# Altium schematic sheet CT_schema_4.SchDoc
size 522 x 390 mm
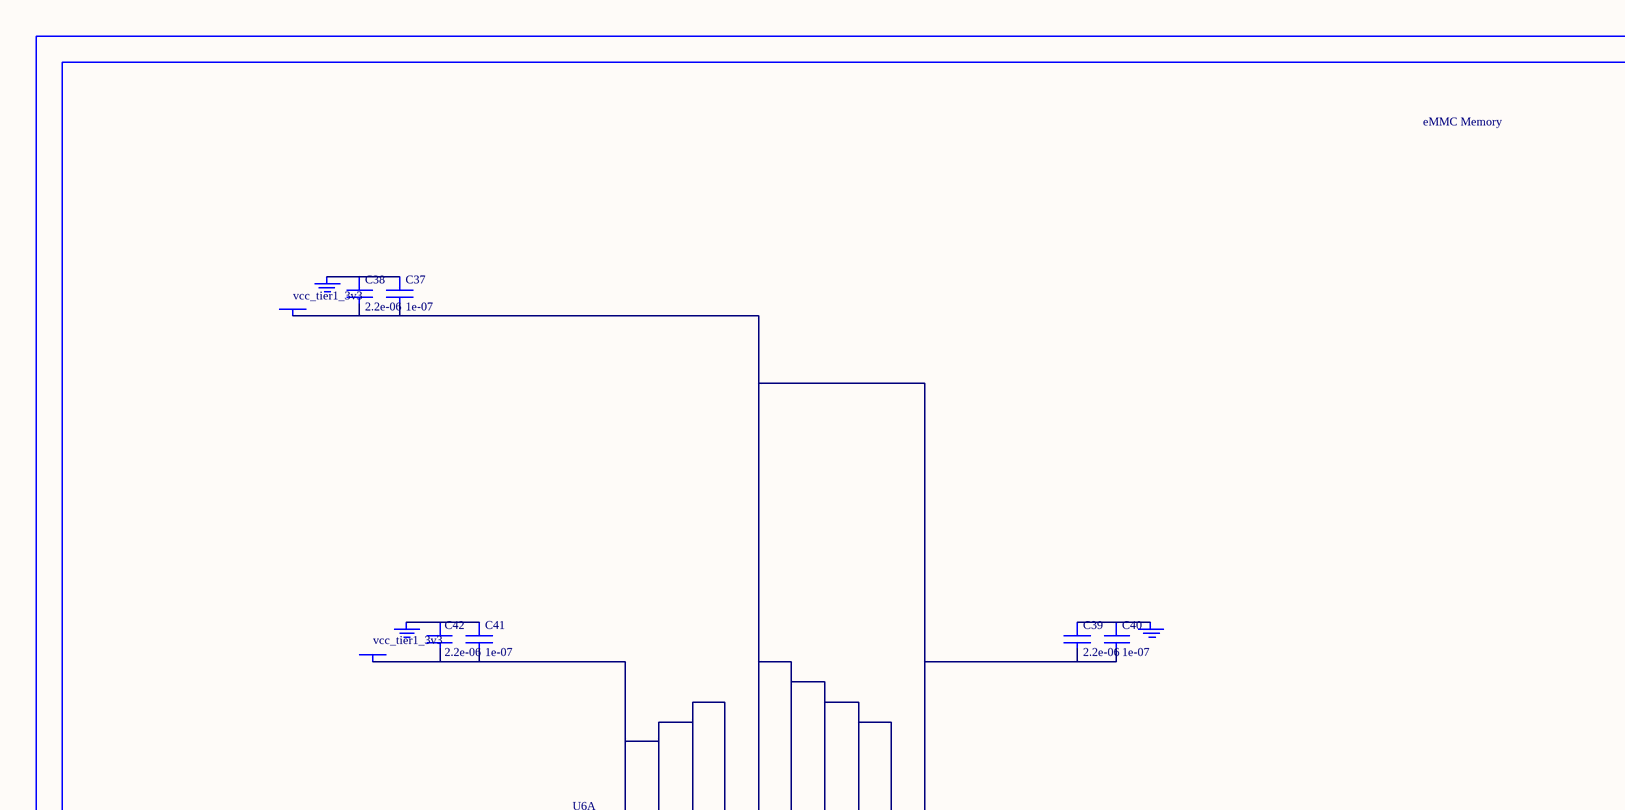
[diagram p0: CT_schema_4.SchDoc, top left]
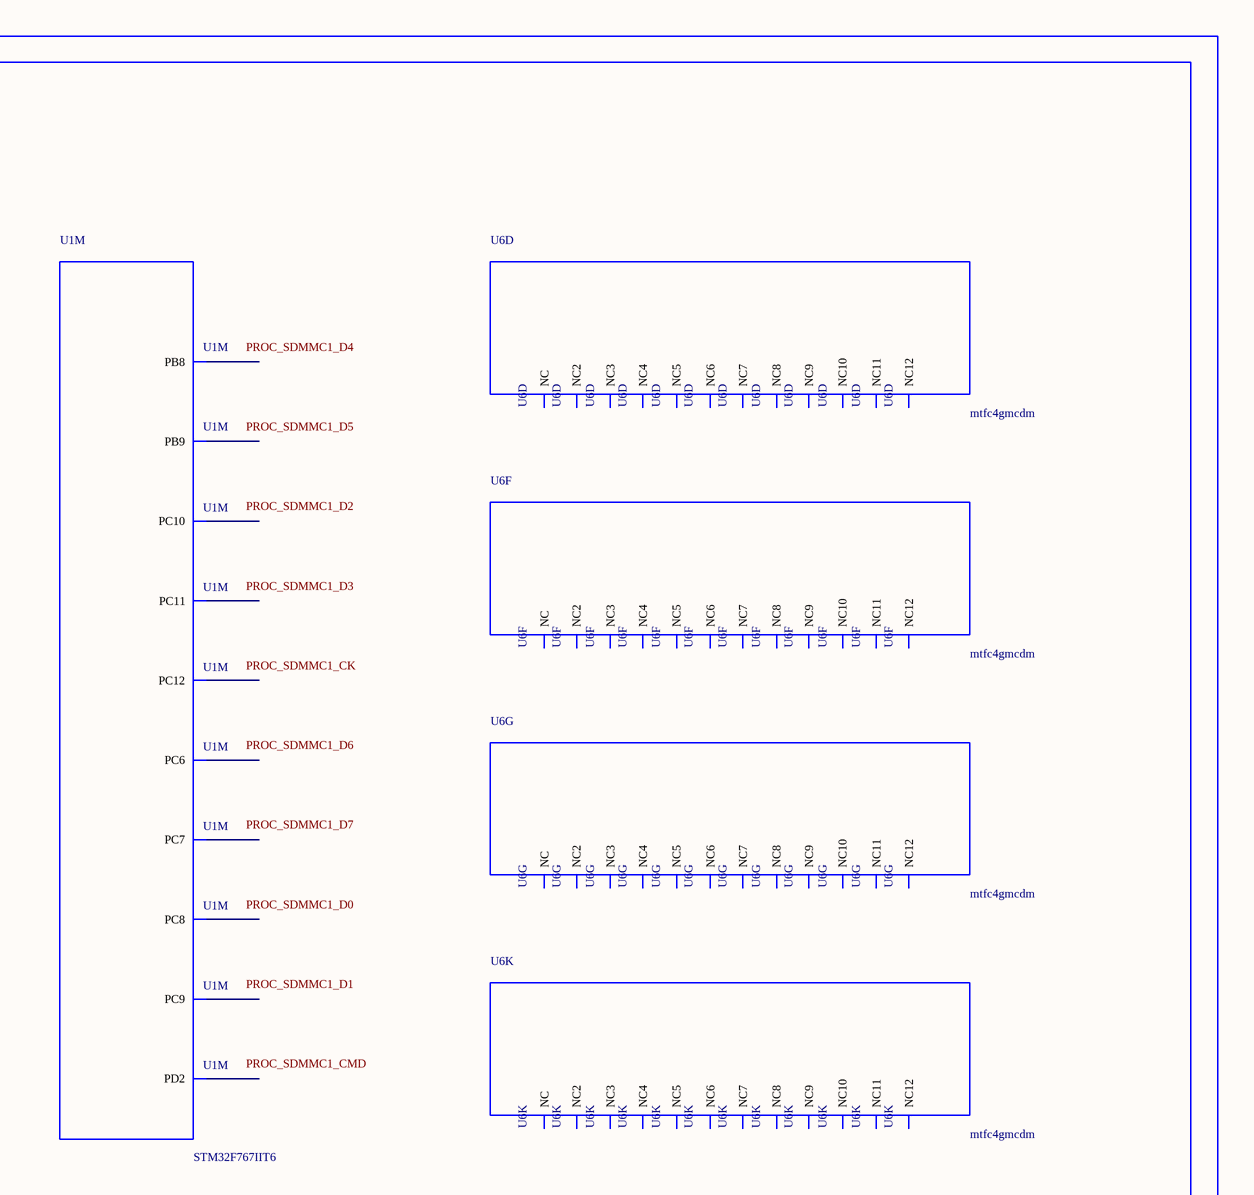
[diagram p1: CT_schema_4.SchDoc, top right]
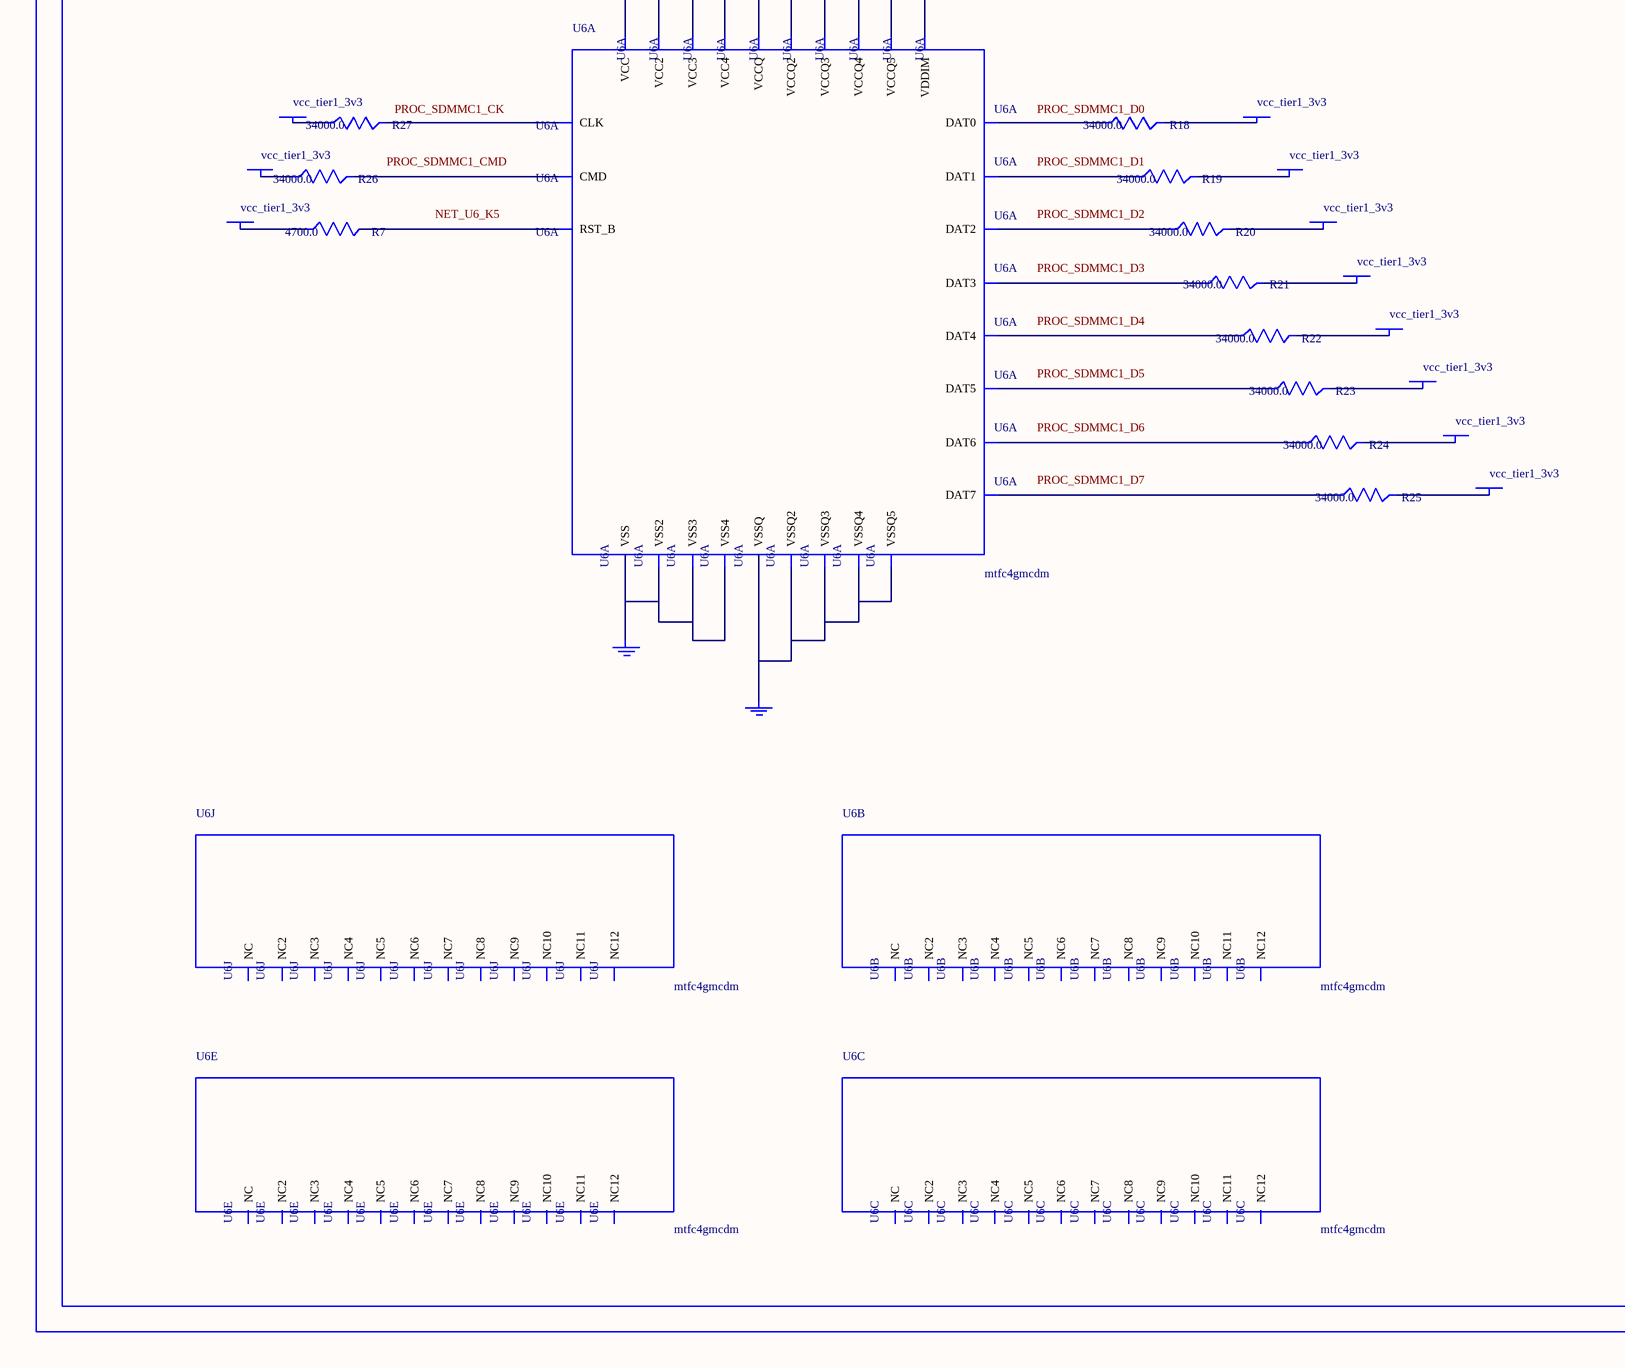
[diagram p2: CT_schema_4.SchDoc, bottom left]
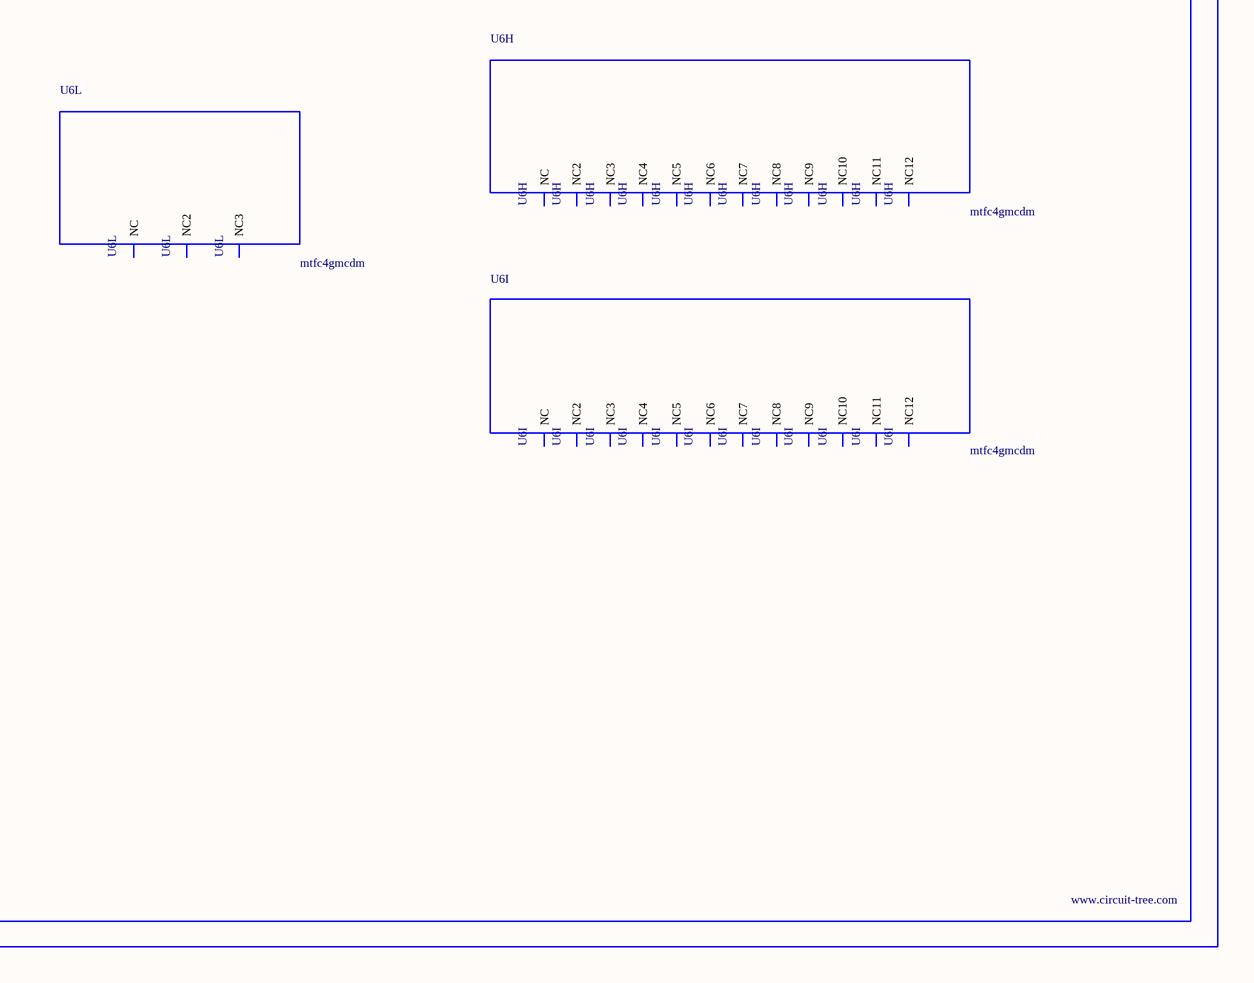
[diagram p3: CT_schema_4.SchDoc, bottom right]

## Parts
BORDER3  (no value)
C37  1e-07  [C0402]
C38  2.2e-06  [C0603]
C39  2.2e-06  [C0603]
C40  1e-07  [C0402]
C41  1e-07  [C0402]
C42  2.2e-06  [C0603]
GND_INSTANCE_3_0  (no value)
GND_INSTANCE_3_1  (no value)
GND_INSTANCE_3_2  (no value)
GND_INSTANCE_3_3  (no value)
GND_INSTANCE_3_4  (no value)
POWER_INSTANCE_3_0  vcc_tier1_3v3
POWER_INSTANCE_3_1  vcc_tier1_3v3
POWER_INSTANCE_3_2  vcc_tier1_3v3
POWER_INSTANCE_3_3  vcc_tier1_3v3
POWER_INSTANCE_3_4  vcc_tier1_3v3
POWER_INSTANCE_3_5  vcc_tier1_3v3
POWER_INSTANCE_3_6  vcc_tier1_3v3
POWER_INSTANCE_3_7  vcc_tier1_3v3
POWER_INSTANCE_3_8  vcc_tier1_3v3
POWER_INSTANCE_3_9  vcc_tier1_3v3
POWER_INSTANCE_3_10  vcc_tier1_3v3
POWER_INSTANCE_3_11  vcc_tier1_3v3
POWER_INSTANCE_3_12  vcc_tier1_3v3
R7  4700.0  [R0603]
R18  34000.0  [R0603]
R19  34000.0  [R0603]
R20  34000.0  [R0603]
R21  34000.0  [R0603]
R22  34000.0  [R0603]
R23  34000.0  [R0603]
R24  34000.0  [R0603]
R25  34000.0  [R0603]
R26  34000.0  [R0603]
R27  34000.0  [R0603]
U1  STM32F767IIT6  [LQFP176]  (part M of 15)
U6  mtfc4gmcdm  [TFBGA-153]  (parts A,B,C,D,E,F,G,H,I,J,K,L of 12)

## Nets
NetC37_1: C37.1 C38.1 GND_INSTANCE_3_0.0(GND)
NetC37_2: C37.2 C38.2 C39.2 C40.2 POWER_INSTANCE_3_0.0(PWR) U6.C2(VDDIM) U6.C6(VCCQ) U6.M4(VCCQ2) U6.N4(VCCQ3) U6.P3(VCCQ4) U6.P5(VCCQ5)
NetC39_1: C39.1 C40.1 GND_INSTANCE_3_1.0(GND)
NetC41_1: C41.1 C42.1 GND_INSTANCE_3_2.0(GND)
NetC41_2: C41.2 C42.2 POWER_INSTANCE_3_1.0(PWR) U6.E6(VCC) U6.F5(VCC2) U6.J10(VCC3) U6.K9(VCC4)
NetGND_INSTANCE_3_3_0: GND_INSTANCE_3_3.0(GND) U6.E7(VSS) U6.G5(VSS2) U6.H10(VSS3) U6.K8(VSS4)
NetGND_INSTANCE_3_4_0: GND_INSTANCE_3_4.0(GND) U6.C4(VSSQ) U6.N2(VSSQ2) U6.N5(VSSQ3) U6.P4(VSSQ4) U6.P6(VSSQ5)
NetPOWER_INSTANCE_3_2_0: POWER_INSTANCE_3_2.0(PWR) R18.2
NetPOWER_INSTANCE_3_3_0: POWER_INSTANCE_3_3.0(PWR) R19.2
NetPOWER_INSTANCE_3_4_0: POWER_INSTANCE_3_4.0(PWR) R20.2
NetPOWER_INSTANCE_3_5_0: POWER_INSTANCE_3_5.0(PWR) R21.2
NetPOWER_INSTANCE_3_6_0: POWER_INSTANCE_3_6.0(PWR) R22.2
NetPOWER_INSTANCE_3_7_0: POWER_INSTANCE_3_7.0(PWR) R23.2
NetPOWER_INSTANCE_3_8_0: POWER_INSTANCE_3_8.0(PWR) R24.2
NetPOWER_INSTANCE_3_9_0: POWER_INSTANCE_3_9.0(PWR) R25.2
NetPOWER_INSTANCE_3_10_0: POWER_INSTANCE_3_10.0(PWR) R26.1
NetPOWER_INSTANCE_3_11_0: POWER_INSTANCE_3_11.0(PWR) R27.1
NetPOWER_INSTANCE_3_12_0: POWER_INSTANCE_3_12.0(PWR) R7.1
NetR7_2: R7.2 U6.K5(RST_B)
NetR18_1: R18.1 U6.A3(DAT0)
NetR19_1: R19.1 U6.A4(DAT1)
NetR20_1: R20.1 U6.A5(DAT2)
NetR21_1: R21.1 U6.B2(DAT3)
NetR22_1: R22.1 U6.B3(DAT4)
NetR23_1: R23.1 U6.B4(DAT5)
NetR24_1: R24.1 U6.B5(DAT6)
NetR25_1: R25.1 U6.B6(DAT7)
NetR26_2: R26.2 U6.M5(CMD)
NetR27_2: R27.2 U6.M6(CLK)

Not connected (* = marked no-connect by the designer): U1 115(PC6) 116(PC7) 117(PC8) 118(PC9) 139(PC10) 140(PC11) 141(PC12) 144(PD2) 167(PB8) 168(PB9); U6 A1(NC) A2(NC7) A6(NC8) A7(NC9) A8(NC10) A9(NC11) A10(NC2) A11(NC3) A12(NC4) A13(NC5) A14(NC6) B1(NC12) B7(NC6) B8(NC7) B9(NC8) B10(NC) B11(NC2) B12(NC3) B13(NC4) B14(NC5) C1(NC9) C3(NC10) C5(NC11) C7(NC12) C8(NC6) C9(NC7) C10(NC) C11(NC2) C12(NC3) C13(NC4) C14(NC5) D1(NC8) D2(NC10) D3(NC11) D4(NC12) D12(NC9) D13(NC) D14(NC2) E1(NC3) E2(NC8) E3(NC9) E5(NC10) E8(NC11) E9(NC12) E10(NC4) E12(NC5) E13(NC6) E14(NC7) F1(NC) F2(NC6) F3(NC7) F10(NC2) F12(NC3) F13(NC4) F14(NC5) G1(NC8) G2(NC11) G3(NC12) G10(NC9) G12(NC10) G13(NC) G14(NC2) H1(NC3) H2(NC7) H3(NC8) H5(NC9) H12(NC4) H13(NC5) H14(NC6) J1(NC10) J2(NC11) J3(NC12) J5(NC4) J12(NC) J13(NC2) J14(NC3) K1(NC5) K2(NC9) K3(NC10) K6(NC11) K7(NC12) K10(NC6) K12(NC7) K13(NC8) K14(NC) L1(NC2) L2(NC6) L3(NC7) L12(NC3) L13(NC4) L14(NC5) M1(NC8) M2(NC9) M3(NC10) M7(NC11) M8(NC12) M9(NC6) M10(NC) M11(NC2) M12(NC3) M13(NC4) M14(NC5) N1(NC7) N3(NC8) N6(NC9) N7(NC10) N8(NC11) N9(NC12) N10(NC) N11(NC2) N12(NC3) N13(NC4) N14(NC5) P1(NC6) P2(NC9) P7(NC10) P8(NC11) P9(NC12) P10(NC7) P11(NC8) P12(NC) P13(NC2) P14(NC3)

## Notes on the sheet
- Labels drawn without touching a wire or pin: NET_U6_K5, PROC_SDMMC1_CK, PROC_SDMMC1_CMD, PROC_SDMMC1_D0, PROC_SDMMC1_D1, PROC_SDMMC1_D2, PROC_SDMMC1_D3, PROC_SDMMC1_D4, PROC_SDMMC1_D5, PROC_SDMMC1_D6, PROC_SDMMC1_D7

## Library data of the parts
BORDER3 = BORDER_PAGE3
C37 C40 C41 = C0402C104K3RACTU
C38 C39 C42 = C0603C225K8RACTU
GND_INSTANCE_3_0-GND_INSTANCE_3_4 = GND
POWER_INSTANCE_3_0-POWER_INSTANCE_3_12 = PWR
R7 = RC0603JR-074K7L
R18-R27 = ERA3ARB3402V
